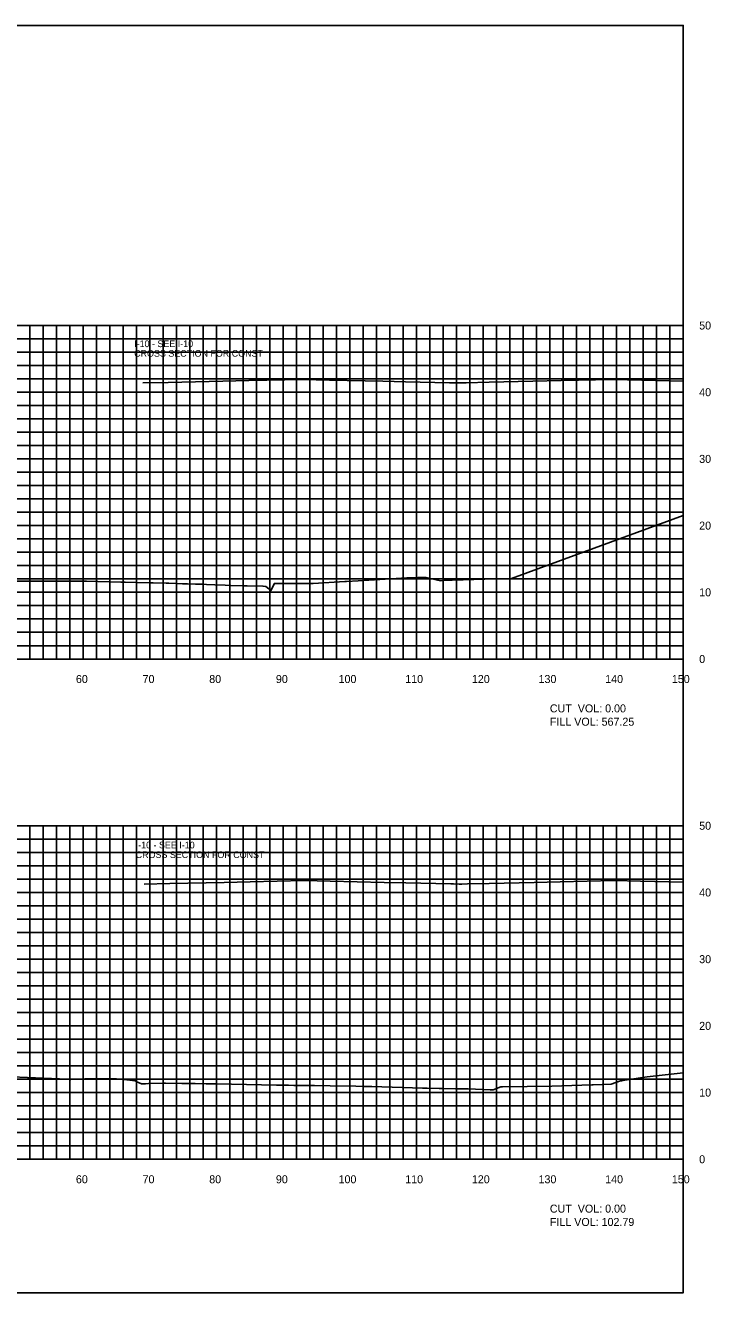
# Model space of a CAD drawing. Extents: x 1797714 to 1804825, y 249015 to 250269.
# Drawn here: x 1803362.3 to 1803465.1, y 250079.4 to 250269.4 of the extents above; entities that cross this region are included whole.
import ezdxf

# ---------------------------------------------------------------- set-up
doc = ezdxf.new("R2010")
doc.units = 0
for name, color, linetype in [('10', 7, 'Continuous'), ('3', 7, 'Continuous'), ('31', 7, 'Continuous'), ('60', 7, 'Continuous'), ('ANNO-TXT', 7, 'Continuous'), ('CL-CNST', 7, 'Continuous'), ('Level 62', 7, 'Continuous'), ('M-ROADS', 7, 'Continuous')]:
    doc.layers.add(name, color=color, linetype=linetype)

msp = doc.modelspace()

# ---------------------------------------------------------------- linework, layer by layer
msp.add_lwpolyline([(1803161, 250079.43), (1803461, 250079.43), (1803461, 250269.43), (1803161, 250269.43)], close=True)
at = {"layer": '60'}
for p, q in [((1803461, 250174.43), (1803461, 250224.43)), ((1803461.06, 250224.43), (1803461, 250224.43)), ((1803461.06, 250214.43), (1803461, 250214.43)), ((1803461.06, 250204.43), (1803461, 250204.43)), ((1803461.06, 250194.43), (1803461, 250194.43)), ((1803461.06, 250184.43), (1803461, 250184.43)), ((1803161, 250174.43), (1803461, 250174.43)), ((1803371, 250174.37), (1803371, 250174.43)), ((1803381, 250174.37), (1803381, 250174.43)), ((1803391, 250174.37), (1803391, 250174.43)), ((1803401, 250174.37), (1803401, 250174.43)), ((1803411, 250174.37), (1803411, 250174.43)), ((1803421, 250174.37), (1803421, 250174.43)), ((1803431, 250174.37), (1803431, 250174.43)), ((1803441, 250174.37), (1803441, 250174.43)), ((1803451, 250174.37), (1803451, 250174.43)), ((1803461, 250174.37), (1803461, 250174.43)), ((1803461.06, 250174.43), (1803461, 250174.43)), ((1803461, 250099.43), (1803461, 250149.43)), ((1803461.06, 250149.43), (1803461, 250149.43)), ((1803461.06, 250139.43), (1803461, 250139.43)), ((1803461.06, 250129.43), (1803461, 250129.43)), ((1803461.06, 250119.43), (1803461, 250119.43)), ((1803461.06, 250109.43), (1803461, 250109.43)), ((1803161, 250099.43), (1803461, 250099.43)), ((1803371, 250099.37), (1803371, 250099.43)), ((1803381, 250099.37), (1803381, 250099.43)), ((1803391, 250099.37), (1803391, 250099.43)), ((1803401, 250099.37), (1803401, 250099.43)), ((1803411, 250099.37), (1803411, 250099.43)), ((1803421, 250099.37), (1803421, 250099.43)), ((1803431, 250099.37), (1803431, 250099.43)), ((1803441, 250099.37), (1803441, 250099.43)), ((1803451, 250099.37), (1803451, 250099.43)), ((1803461, 250099.37), (1803461, 250099.43)), ((1803461.06, 250099.43), (1803461, 250099.43))]:
    msp.add_line(p, q, dxfattribs=at)
at = {"layer": 'CL-CNST'}
for points in [[(1803379.93, 250215.82), (1803383.75, 250215.9), (1803391.93, 250216.08), (1803395.84, 250216.17), (1803403.93, 250216.35), (1803407.93, 250216.26), (1803415.94, 250216.08), (1803419.34, 250216.01), (1803425.94, 250215.86), (1803426.37, 250215.85), (1803427.18, 250215.83), (1803427.18, 250215.83), (1803427.19, 250215.83), (1803427.62, 250215.84), (1803428.44, 250215.86), (1803431.91, 250215.94), (1803438.44, 250216.08), (1803442.69, 250216.17), (1803450.44, 250216.34), (1803454.78, 250216.25), (1803461, 250216.11)], [(1803380.16, 250140.67), (1803384, 250140.75), (1803392.16, 250140.93), (1803396.02, 250141.02), (1803404.16, 250141.2), (1803408.03, 250141.11), (1803416.16, 250140.93), (1803419.4, 250140.86), (1803426.16, 250140.71), (1803426.56, 250140.7), (1803427.4, 250140.69), (1803427.4, 250140.69), (1803427.41, 250140.69), (1803427.81, 250140.69), (1803428.66, 250140.71), (1803431.91, 250140.78), (1803438.66, 250140.93), (1803442.57, 250141.02), (1803450.66, 250141.2), (1803454.59, 250141.11), (1803461, 250140.97)]]:
    msp.add_lwpolyline(points, dxfattribs=at)
at = {"layer": 'Level 62'}
for p, q in [((1803161, 250224.43), (1803461, 250224.43)), ((1803363, 250174.43), (1803363, 250224.43)), ((1803365, 250174.43), (1803365, 250224.43)), ((1803367, 250174.43), (1803367, 250224.43)), ((1803369, 250174.43), (1803369, 250224.43)), ((1803371, 250174.43), (1803371, 250224.43)), ((1803373, 250174.43), (1803373, 250224.43)), ((1803375, 250174.43), (1803375, 250224.43)), ((1803377, 250174.43), (1803377, 250224.43)), ((1803379, 250174.43), (1803379, 250224.43)), ((1803381, 250174.43), (1803381, 250224.43)), ((1803383, 250174.43), (1803383, 250224.43)), ((1803385, 250174.43), (1803385, 250224.43)), ((1803387, 250174.43), (1803387, 250224.43)), ((1803389, 250174.43), (1803389, 250224.43)), ((1803391, 250174.43), (1803391, 250224.43)), ((1803393, 250174.43), (1803393, 250224.43)), ((1803395, 250174.43), (1803395, 250224.43)), ((1803397, 250174.43), (1803397, 250224.43)), ((1803399, 250174.43), (1803399, 250224.43)), ((1803401, 250174.43), (1803401, 250224.43)), ((1803403, 250174.43), (1803403, 250224.43)), ((1803405, 250174.43), (1803405, 250224.43)), ((1803407, 250174.43), (1803407, 250224.43)), ((1803409, 250174.43), (1803409, 250224.43)), ((1803411, 250174.43), (1803411, 250224.43)), ((1803413, 250174.43), (1803413, 250224.43)), ((1803415, 250174.43), (1803415, 250224.43)), ((1803417, 250174.43), (1803417, 250224.43)), ((1803419, 250174.43), (1803419, 250224.43)), ((1803421, 250174.43), (1803421, 250224.43)), ((1803423, 250174.43), (1803423, 250224.43)), ((1803425, 250174.43), (1803425, 250224.43)), ((1803427, 250174.43), (1803427, 250224.43)), ((1803429, 250174.43), (1803429, 250224.43)), ((1803431, 250174.43), (1803431, 250224.43)), ((1803433, 250174.43), (1803433, 250224.43)), ((1803435, 250174.43), (1803435, 250224.43)), ((1803437, 250174.43), (1803437, 250224.43)), ((1803439, 250174.43), (1803439, 250224.43)), ((1803441, 250174.43), (1803441, 250224.43)), ((1803443, 250174.43), (1803443, 250224.43)), ((1803445, 250174.43), (1803445, 250224.43)), ((1803447, 250174.43), (1803447, 250224.43)), ((1803449, 250174.43), (1803449, 250224.43)), ((1803451, 250174.43), (1803451, 250224.43)), ((1803453, 250174.43), (1803453, 250224.43)), ((1803455, 250174.43), (1803455, 250224.43)), ((1803457, 250174.43), (1803457, 250224.43)), ((1803459, 250174.43), (1803459, 250224.43)), ((1803461, 250174.43), (1803461, 250224.43)), ((1803161, 250222.43), (1803461, 250222.43)), ((1803161, 250220.43), (1803461, 250220.43)), ((1803161, 250218.43), (1803461, 250218.43)), ((1803161, 250216.43), (1803461, 250216.43)), ((1803161, 250214.43), (1803461, 250214.43)), ((1803161, 250212.43), (1803461, 250212.43)), ((1803161, 250210.43), (1803461, 250210.43)), ((1803161, 250208.43), (1803461, 250208.43)), ((1803161, 250206.43), (1803461, 250206.43)), ((1803161, 250204.43), (1803461, 250204.43)), ((1803161, 250202.43), (1803461, 250202.43)), ((1803161, 250200.43), (1803461, 250200.43)), ((1803161, 250198.43), (1803461, 250198.43)), ((1803161, 250196.43), (1803461, 250196.43)), ((1803161, 250194.43), (1803461, 250194.43)), ((1803161, 250192.43), (1803461, 250192.43)), ((1803161, 250190.43), (1803461, 250190.43)), ((1803161, 250188.43), (1803461, 250188.43)), ((1803161, 250186.43), (1803461, 250186.43)), ((1803161, 250184.43), (1803461, 250184.43)), ((1803161, 250182.43), (1803461, 250182.43)), ((1803161, 250180.43), (1803461, 250180.43)), ((1803161, 250178.43), (1803461, 250178.43)), ((1803161, 250176.43), (1803461, 250176.43)), ((1803161, 250174.43), (1803461, 250174.43)), ((1803161, 250149.43), (1803461, 250149.43)), ((1803363, 250099.43), (1803363, 250149.43)), ((1803365, 250099.43), (1803365, 250149.43)), ((1803367, 250099.43), (1803367, 250149.43)), ((1803369, 250099.43), (1803369, 250149.43)), ((1803371, 250099.43), (1803371, 250149.43)), ((1803373, 250099.43), (1803373, 250149.43)), ((1803375, 250099.43), (1803375, 250149.43)), ((1803377, 250099.43), (1803377, 250149.43)), ((1803379, 250099.43), (1803379, 250149.43)), ((1803381, 250099.43), (1803381, 250149.43)), ((1803383, 250099.43), (1803383, 250149.43)), ((1803385, 250099.43), (1803385, 250149.43)), ((1803387, 250099.43), (1803387, 250149.43)), ((1803389, 250099.43), (1803389, 250149.43)), ((1803391, 250099.43), (1803391, 250149.43)), ((1803393, 250099.43), (1803393, 250149.43)), ((1803395, 250099.43), (1803395, 250149.43)), ((1803397, 250099.43), (1803397, 250149.43)), ((1803399, 250099.43), (1803399, 250149.43)), ((1803401, 250099.43), (1803401, 250149.43)), ((1803403, 250099.43), (1803403, 250149.43)), ((1803405, 250099.43), (1803405, 250149.43)), ((1803407, 250099.43), (1803407, 250149.43)), ((1803409, 250099.43), (1803409, 250149.43)), ((1803411, 250099.43), (1803411, 250149.43)), ((1803413, 250099.43), (1803413, 250149.43)), ((1803415, 250099.43), (1803415, 250149.43)), ((1803417, 250099.43), (1803417, 250149.43)), ((1803419, 250099.43), (1803419, 250149.43)), ((1803421, 250099.43), (1803421, 250149.43)), ((1803423, 250099.43), (1803423, 250149.43)), ((1803425, 250099.43), (1803425, 250149.43)), ((1803427, 250099.43), (1803427, 250149.43)), ((1803429, 250099.43), (1803429, 250149.43)), ((1803431, 250099.43), (1803431, 250149.43)), ((1803433, 250099.43), (1803433, 250149.43)), ((1803435, 250099.43), (1803435, 250149.43)), ((1803437, 250099.43), (1803437, 250149.43)), ((1803439, 250099.43), (1803439, 250149.43)), ((1803441, 250099.43), (1803441, 250149.43)), ((1803443, 250099.43), (1803443, 250149.43)), ((1803445, 250099.43), (1803445, 250149.43)), ((1803447, 250099.43), (1803447, 250149.43)), ((1803449, 250099.43), (1803449, 250149.43)), ((1803451, 250099.43), (1803451, 250149.43)), ((1803453, 250099.43), (1803453, 250149.43)), ((1803455, 250099.43), (1803455, 250149.43)), ((1803457, 250099.43), (1803457, 250149.43)), ((1803459, 250099.43), (1803459, 250149.43)), ((1803461, 250099.43), (1803461, 250149.43)), ((1803161, 250147.43), (1803461, 250147.43)), ((1803161, 250145.43), (1803461, 250145.43)), ((1803161, 250143.43), (1803461, 250143.43)), ((1803161, 250141.43), (1803461, 250141.43)), ((1803161, 250139.43), (1803461, 250139.43)), ((1803161, 250137.43), (1803461, 250137.43)), ((1803161, 250135.43), (1803461, 250135.43)), ((1803161, 250133.43), (1803461, 250133.43)), ((1803161, 250131.43), (1803461, 250131.43)), ((1803161, 250129.43), (1803461, 250129.43)), ((1803161, 250127.43), (1803461, 250127.43)), ((1803161, 250125.43), (1803461, 250125.43)), ((1803161, 250123.43), (1803461, 250123.43)), ((1803161, 250121.43), (1803461, 250121.43)), ((1803161, 250119.43), (1803461, 250119.43)), ((1803161, 250117.43), (1803461, 250117.43)), ((1803161, 250115.43), (1803461, 250115.43)), ((1803161, 250113.43), (1803461, 250113.43)), ((1803161, 250111.43), (1803461, 250111.43)), ((1803161, 250109.43), (1803461, 250109.43)), ((1803161, 250107.43), (1803461, 250107.43)), ((1803161, 250105.43), (1803461, 250105.43)), ((1803161, 250103.43), (1803461, 250103.43)), ((1803161, 250101.43), (1803461, 250101.43)), ((1803161, 250099.43), (1803461, 250099.43))]:
    msp.add_line(p, q, dxfattribs=at)
at = {"layer": 'M-ROADS'}
for points in [[(1803359.45, 250186.1), (1803362.33, 250186.1), (1803364.18, 250186.1), (1803364.26, 250186.1), (1803365.5, 250186.1), (1803366.49, 250186.09), (1803367.27, 250186.09), (1803371.14, 250186.08), (1803371.47, 250186.08), (1803376.63, 250185.97), (1803377.18, 250185.96), (1803377.31, 250185.96), (1803378.88, 250185.92), (1803381.02, 250185.87), (1803381.11, 250185.86), (1803381.48, 250185.85), (1803383.45, 250185.79), (1803383.83, 250185.78), (1803385.88, 250185.72), (1803386.66, 250185.7), (1803387.82, 250185.66), (1803388.98, 250185.63), (1803389.48, 250185.61), (1803390.73, 250185.55), (1803392.3, 250185.51), (1803393.16, 250185.47), (1803395.12, 250185.42), (1803395.22, 250185.41), (1803395.58, 250185.41), (1803397.95, 250185.34), (1803398.01, 250185.33), (1803398.41, 250185.32), (1803398.83, 250184.93), (1803399.14, 250184.65), (1803399.59, 250185.58), (1803399.67, 250185.76), (1803399.68, 250185.77), (1803403.92, 250185.76), (1803405.5, 250185.76), (1803410.23, 250186.05), (1803410.5, 250186.05), (1803412.26, 250186.14), (1803419.55, 250186.58), (1803421.2, 250186.64), (1803421.24, 250186.64), (1803421.6, 250186.64), (1803421.7, 250186.64), (1803422.45, 250186.63), (1803424.57, 250186.17), (1803425.01, 250186.2), (1803426.36, 250186.25), (1803431.22, 250186.42), (1803432.4, 250186.45), (1803432.82, 250186.44), (1803432.99, 250186.45), (1803435.27, 250186.51), (1803461, 250195.96)], [(1803355.42, 250112), (1803367.43, 250111.49), (1803369.15, 250111.4), (1803371.26, 250111.48), (1803371.45, 250111.48), (1803375.83, 250111.5), (1803375.98, 250111.5), (1803376.32, 250111.44), (1803376.72, 250111.44), (1803378.78, 250111.2), (1803379.03, 250111.04), (1803379.75, 250110.74), (1803380.26, 250110.76), (1803380.32, 250110.76), (1803380.81, 250110.77), (1803383.06, 250110.83), (1803383.35, 250110.82), (1803385.8, 250110.8), (1803387.8, 250110.78), (1803389.45, 250110.76), (1803390.84, 250110.75), (1803390.99, 250110.75), (1803399.98, 250110.55), (1803400.57, 250110.53), (1803400.61, 250110.53), (1803400.78, 250110.53), (1803401.04, 250110.52), (1803401.43, 250110.52), (1803401.5, 250110.52), (1803401.81, 250110.52), (1803402.59, 250110.51), (1803403.17, 250110.51), (1803404.66, 250110.49), (1803405.71, 250110.48), (1803408.04, 250110.46), (1803411.88, 250110.38), (1803413.08, 250110.35), (1803413.75, 250110.33), (1803413.76, 250110.33), (1803413.8, 250110.33), (1803414.24, 250110.33), (1803414.26, 250110.33), (1803414.27, 250110.33), (1803414.28, 250110.33), (1803421.91, 250110.09), (1803422.61, 250110.07), (1803424.38, 250110.04), (1803424.82, 250110.03), (1803426.86, 250110), (1803427.19, 250110), (1803428.72, 250109.99), (1803432.03, 250109.86), (1803432.27, 250109.84), (1803432.49, 250109.83), (1803432.49, 250109.83), (1803433.64, 250110.31), (1803433.91, 250110.31), (1803441.29, 250110.38), (1803447.3, 250110.59), (1803447.49, 250110.59), (1803450.21, 250110.68), (1803451.62, 250111.2), (1803451.8, 250111.21), (1803452.25, 250111.27), (1803455.62, 250111.78), (1803461, 250112.39)]]:
    msp.add_lwpolyline(points, dxfattribs=at)

# ---------------------------------------------------------------- texts
at = {"layer": '10'}
for s, p in [('60', (1803369.9, 250170.83)), ('70', (1803379.9, 250170.83)), ('80', (1803389.9, 250170.83)), ('90', (1803399.9, 250170.83)), ('100', (1803409.3, 250170.83)), ('110', (1803419.3, 250170.83)), ('120', (1803429.3, 250170.83)), ('130', (1803439.3, 250170.83)), ('140', (1803449.3, 250170.83)), ('150', (1803459.3, 250170.83)), ('60', (1803369.9, 250095.83)), ('70', (1803379.9, 250095.83)), ('80', (1803389.9, 250095.83)), ('90', (1803399.9, 250095.83)), ('100', (1803409.3, 250095.83)), ('110', (1803419.3, 250095.83)), ('120', (1803429.3, 250095.83)), ('130', (1803439.3, 250095.83)), ('140', (1803449.3, 250095.83)), ('150', (1803459.3, 250095.83))]:
    msp.add_text(s, height=1.2, dxfattribs=at).set_placement(p)
at = {"layer": '3'}
for s, p in [('CROSS SECTION FOR CONST ', (1803378.64, 250219.75)), ('I-10 - SEE I-10 ', (1803378.64, 250221.19)), ('I-10 - SEE I-10 ', (1803378.87, 250146.04)), ('CROSS SECTION FOR CONST ', (1803378.87, 250144.59))]:
    msp.add_text(s, height=1, dxfattribs=at).set_placement(p)
at = {"layer": '31'}
for s, p in [('50', (1803463.4, 250223.83)), ('40', (1803463.4, 250213.83)), ('30', (1803463.4, 250203.83)), ('20', (1803463.4, 250193.83)), ('10', (1803463.4, 250183.83)), ('0', (1803463.4, 250173.83)), ('50', (1803463.4, 250148.83)), ('40', (1803463.4, 250138.83)), ('30', (1803463.4, 250128.83)), ('20', (1803463.4, 250118.83)), ('10', (1803463.4, 250108.83)), ('0', (1803463.4, 250098.83))]:
    msp.add_text(s, height=1.2, dxfattribs=at).set_placement(p)
at = {"layer": 'ANNO-TXT'}
for s, p in [('CUT  VOL: 0.00', (1803441, 250166.43)), ('FILL VOL: 567.25', (1803441, 250164.43)), ('CUT  VOL: 0.00', (1803441, 250091.43)), ('FILL VOL: 102.79', (1803441, 250089.43))]:
    msp.add_text(s, height=1.2, dxfattribs=at).set_placement(p)

doc.saveas('drawing.dxf')
